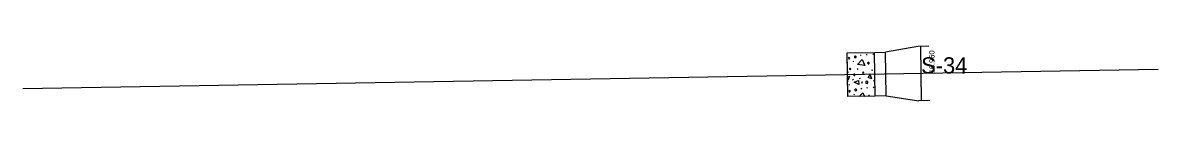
# Model space of a CAD drawing. Extents: x 925371 to 925937, y 853654 to 858024.
# Drawn here: x 925606.8 to 925815.1, y 855973.2 to 855983.2 of the extents above; entities that cross this region are included whole.
import ezdxf

# ---------------------------------------------------------------- set-up
doc = ezdxf.new("R2010")
doc.units = 0
for name, color, linetype in [('DitchPavt', 7, 'Continuous'), ('GPKDrBack_dp', 7, 'Continuous'), ('GPKDrBottom_dp', 7, 'Continuous'), ('GPKDrCellIns_dp', 7, 'Continuous'), ('GPKDrFront_dp', 7, 'Continuous'), ('InletClosedFlume', 7, 'Continuous'), ('Miscellaneous6', 7, 'Continuous'), ('NonPlottingEle_dp', 7, 'Continuous')]:
    doc.layers.add(name, color=color, linetype=linetype)

msp = doc.modelspace()

# ---------------------------------------------------------------- linework, layer by layer
at = {"layer": 'DitchPavt'}
for p, q in [((925760.43, 855981.47), (925760.58, 855981.59)), ((925761.68, 855981.56), (925761.47, 855981.65)), ((925762.68, 855981.7), (925762.81, 855981.8)), ((925758.11, 855980.12), (925758.03, 855980.16)), ((925759.1, 855980.36), (925759.23, 855980.45)), ((925759.85, 855979), (925759.99, 855979.09)), ((925758.11, 855978.39), (925758.26, 855978.5)), ((925758.99, 855977.01), (925759.14, 855977.14)), ((925760.25, 855977.25), (925760.41, 855977.35)), ((925762.7, 855978.73), (925762.47, 855978.82)), ((925763.04, 855977.08), (925763.08, 855977.11)), ((925758.13, 855976.87), (925758.08, 855976.96)), ((925758.18, 855976.67), (925758.09, 855976.71)), ((925758.49, 855976), (925758.27, 855976.09)), ((925760.53, 855975.38), (925760.69, 855975.49)), ((925761.78, 855975.47), (925761.58, 855975.56)), ((925762.78, 855975.61), (925762.92, 855975.7)), ((925762.85, 855976.81), (925763.01, 855976.91)), ((925758.21, 855974.03), (925758.13, 855974.06)), ((925759.21, 855974.27), (925759.33, 855974.36))]:
    msp.add_line(p, q, dxfattribs=at)
for points in [[(925763.13, 855974.01), (925758.14, 855973.92), (925758, 855981.96), (925763, 855982.05)], [(925758.28, 855980.91), (925758.39, 855980.88), (925758.47, 855980.97), (925758.45, 855981.07), (925758.37, 855981.16), (925758.29, 855981.13), (925758.25, 855981.09), (925758.22, 855981.03), (925758.22, 855981), (925758.28, 855980.91)], [(925759.36, 855981.13), (925759.5, 855981.08), (925759.62, 855981.12), (925759.64, 855981.23), (925759.62, 855981.3), (925759.52, 855981.4), (925759.38, 855981.39), (925759.31, 855981.3), (925759.31, 855981.22), (925759.36, 855981.13)], [(925758.53, 855978.94), (925758.63, 855978.94), (925758.64, 855979.02), (925758.63, 855979.1), (925758.53, 855979.16), (925758.48, 855979.13), (925758.44, 855979.07), (925758.44, 855978.97), (925758.53, 855978.94)], [(925761.26, 855979.68), (925759.88, 855979.84), (925760.75, 855980.73), (925761.26, 855979.68)], [(925761.83, 855979.98), (925761.94, 855979.95), (925762.05, 855980.03), (925762.01, 855980.14), (925761.97, 855980.22), (925761.89, 855980.22), (925761.78, 855980.19), (925761.73, 855980.09), (925761.78, 855980), (925761.83, 855979.98)], [(925758.07, 855977.5), (925758.42, 855977.66), (925758.13, 855976.87)], [(925759.37, 855977.83), (925759.4, 855977.86), (925759.43, 855977.96), (925759.38, 855978.05), (925759.33, 855978.08), (925759.24, 855978.05), (925759.21, 855977.92), (925759.24, 855977.86), (925759.3, 855977.83), (925759.37, 855977.83)], [(925760.95, 855978.2), (925761.05, 855978.3), (925761.04, 855978.39), (925760.93, 855978.45), (925760.83, 855978.36), (925760.86, 855978.29), (925760.88, 855978.23), (925760.95, 855978.2), (925760.92, 855978.2)], [(925762.46, 855977.17), (925761.84, 855977.47), (925762.19, 855977.94), (925762.46, 855977.17)], [(925758.39, 855974.81), (925758.5, 855974.78), (925758.57, 855974.88), (925758.56, 855974.97), (925758.48, 855975.07), (925758.4, 855975.03), (925758.35, 855975), (925758.32, 855974.94), (925758.32, 855974.91), (925758.39, 855974.81)], [(925760.16, 855976.16), (925759.29, 855976.58), (925760.09, 855976.91), (925760.16, 855976.16)], [(925759.46, 855975.04), (925759.6, 855974.99), (925759.73, 855975.02), (925759.74, 855975.13), (925759.72, 855975.21), (925759.63, 855975.3), (925759.49, 855975.3), (925759.41, 855975.21), (925759.41, 855975.13), (925759.46, 855975.04)], [(925760.75, 855976.45), (925760.79, 855976.57), (925760.73, 855976.57), (925760.65, 855976.54), (925760.69, 855976.46), (925760.75, 855976.45)], [(925761.44, 855976.4), (925761.7, 855976.34), (925761.8, 855976.45), (925761.79, 855976.53), (925761.79, 855976.7), (925761.6, 855976.78), (925761.43, 855976.73), (925761.39, 855976.62), (925761.39, 855976.49), (925761.44, 855976.4)], [(925760.19, 855973.96), (925760.86, 855974.64), (925761.18, 855973.97)], [(925762.14, 855973.99), (925762.12, 855974.05), (925762.07, 855974.13), (925761.99, 855974.13), (925761.88, 855974.09), (925761.84, 855974), (925761.85, 855973.98)]]:
    msp.add_lwpolyline(points, dxfattribs=at)
at = {"layer": 'GPKDrBack_dp'}
msp.add_line((925765.07, 855978.06), (925765.07, 855978.06), dxfattribs=at)
at = {"layer": 'GPKDrBottom_dp'}
msp.add_line((925771.56, 855978.17), (925771.56, 855978.17), dxfattribs=at)
at = {"layer": 'GPKDrCellIns_dp'}
msp.add_line((925771.56, 855978.17), (925771.56, 855978.17), dxfattribs=at)
at = {"layer": 'GPKDrFront_dp'}
msp.add_line((925773.06, 855978.2), (925773.06, 855978.2), dxfattribs=at)
at = {"layer": 'InletClosedFlume'}
for p, q in [((925770.98, 855983.16), (925765, 855982.08)), ((925765.13, 855974.04), (925765, 855982.08)), ((925772.98, 855983.2), (925770.98, 855983.16)), ((925771.65, 855973.17), (925771.48, 855983.17)), ((925765.13, 855974.04), (925771.15, 855973.16)), ((925773.15, 855973.2), (925771.15, 855973.16))]:
    msp.add_line(p, q, dxfattribs=at)
msp.add_lwpolyline([(925765.13, 855974.04), (925763.13, 855974.01), (925763, 855982.05), (925765, 855982.08)], dxfattribs=at)
at = {"layer": 'Miscellaneous6'}
msp.add_line((925815.06, 855978.91), (925606.77, 855975.37), dxfattribs=at)

# ---------------------------------------------------------------- texts
at = {"layer": 'NonPlottingEle_dp'}
msp.add_text('S-34', height=3, dxfattribs=at).set_placement((925771.56, 855978.17))
msp.add_text('16.960', height=1, rotation=90.9741, dxfattribs=at).set_placement((925774.07, 855978.22))

doc.saveas('drawing.dxf')
